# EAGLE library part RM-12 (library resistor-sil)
Divider 7 Murata M-Type
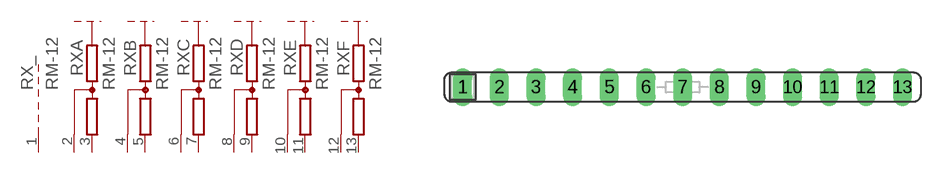
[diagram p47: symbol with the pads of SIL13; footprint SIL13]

Designator prefix RX; gates A=SIL-M B=SIL-M C=SIL-M D=SIL-M E=SIL-M F=SIL-M _=R-P

## RM-12 (OC_FARNELL: unknown; OC_NEWARK: unknown)  [SIL13]
1  _:2  pas
2  A:M1  pas
3  A:M2  pas
4  B:M1  pas
5  B:M2  pas
6  C:M1  pas
7  C:M2  pas
8  D:M1  pas
9  D:M2  pas
10  E:M1  pas
11  E:M2  pas
12  F:M1  pas
13  F:M2  pas

## Footprint SIL13 (pad centres in mm)
Single In Line
drill 0.813 long: 1 -15.24,0; 2 -12.7,0; 3 -10.16,0; 4 -7.62,0; 5 -5.08,0; 6 -2.54,0; 7 0,0; 8 2.54,0; 9 5.08,0; 10 7.62,0; 11 10.16,0; 12 12.7,0; 13 15.24,0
